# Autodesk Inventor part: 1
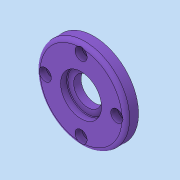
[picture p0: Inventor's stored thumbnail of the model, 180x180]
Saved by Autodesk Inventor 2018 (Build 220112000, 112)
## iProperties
Created: 2020-01
Part Number: 1
Material: 일반
Document SubType Name: Modeling
Designer: 604
Density: 1 g/cm^3
Appearance: 보라색
Author: 604
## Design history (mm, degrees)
sketch "스케치1"
  geometry: C1 r 35 at (0, 0); 1 further point
  constraints: 1 centre point, 1 coincident
  dimensions: "d0" = 70 diameter of C1
extrude "돌출1" new body sketch "스케치1" stored distance "d1" = 14; taper "d2" = 0 deg
fillet "모깎기1" dims "d3" = 3
sketch "스케치2"
  geometry: C1 r 16 at (0, 0); 1 further point
  constraints: 1 centre point, 1 coincident
  dimensions: "d4" = 32 diameter of C1
extrude "돌출2" cut sketch "스케치2" distance "d5" = 5.2; taper "d6" = 0 deg
sketch "스케치3"
  geometry: C1 r 11 at (0, 0); 1 further point
  constraints: 1 centre point, 1 coincident
  dimensions: "d7" = 22 diameter of C1
extrude "돌출3" cut sketch "스케치3" distance "d8" = 5.8; taper "d9" = 0 deg
sketch "스케치4"
  geometry: C1 r 18 at (0, 0); 1 further point
  constraints: 1 centre point, 1 coincident
  dimensions: "d10" = 36 diameter of C1
extrude "돌출4" cut sketch "스케치4" distance "d11" = 3; taper "d12" = 0 deg
fillet "모깎기2" dims "d13" = 3
sketch "스케치5"
  geometry: C1 r 35 at (0, 0); C2 r 23.5 at (0, 0); 1 further point
  constraints: 2 centre point, 2 coincident
  dimensions: "d14" = 47 diameter of C2
extrude "돌출5" cut sketch "스케치5" distance "d15" = 4; taper "d16" = 0 deg
sketch "스케치6"
  geometry: A1 r 28 centre (0, 0) between (0, 28) and (-28, 0); 3 further points
  constraints: 4 point on circle, 1 centre point, 1 coincident
  dimensions: "d17" = 56 diameter of A1
hole "구멍1" sketch "스케치6" at (0, 28), (-28, 0), (0, -28), (28, 0) diameter "d18" = 9.5; stored, may be unused: countersink angle "d22" = 90 deg, drill point angle "d24" = 0 deg; dims "d19" = 6, "d20" = 4, "d21" = 2, "d23" = 5.4
sketch "스케치7"
  geometry: C1 r 4.75 at (0, 0) reference; C2 r 4.75 at (28, -28) reference; C3 r 4.75 at (0, -56) reference; A1 r 4.75 centre (-28, -28) between (-31.883, -30.736) and (-31.883, -25.264) reference; 5 further points
  constraints: 4 coincident
hole "구멍2" sketch "스케치7" at (0, 0), (28, -28), (0, -56), (-28, -28) diameter "d25" = 5.5; stored, may be unused: countersink angle "d29" = 90 deg, drill point angle "d31" = 0 deg; dims "d26" = 6, "d27" = 4, "d28" = 2, "d30" = 5.4
fillet "모깎기3" dims "d32" = 0.5
node "솔리드1"
